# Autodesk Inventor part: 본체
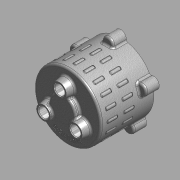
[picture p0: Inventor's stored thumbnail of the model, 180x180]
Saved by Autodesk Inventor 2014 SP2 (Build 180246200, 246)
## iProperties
Created: 2015-11
Part Number: 본체
Document SubType Name: 모델링
Designer: mdu
Material: 알루미늄 6061
Density: 1 g/cm^3
Appearance: 알루미늄 - 평지
변환 표준: STEP AP214IS
파일 이름: C:\Users\SeoGD\Desktop\?쒗뿕\紐몄껜.stp
전처리기: Build: 253, Release: 2010 SP1 - Date: Wed 07/29/2009
전송 단위: 밀리미터
불확실성: 0.01
Author: mdu
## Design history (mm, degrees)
sketch "스케치2"
  geometry: C1 r 50 at (0, 0); 1 further point
  constraints: 1 centre point, 1 coincident
  dimensions: "d9" = 100 diameter of C1
extrude "돌출2" new body sketch "스케치2" distance "d10" = 80; taper "d11" = 0 deg
feature "쉘1" dims "d12" = 5
sketch "스케치3" dims "d13" = 55
  geometry: C1 r 7.5 at (0, 27.5); C2 r 12.5 at (0, 27.5); 2 further points
  constraints: 2 centre point, 2 coincident, 2 vertical alignment, 2 other
  dimensions: "d14" = 15 diameter of C1; "d15" = 25 diameter of C2
extrude "돌출3" join sketch "스케치3" distance "d16" = 12; taper "d17" = -10 deg
hole "구멍2" diameter "d20" = 15; stored, may be unused: countersink angle "d24" = 90 deg, drill point angle "d26" = 118 deg; dims "d18" = 10, "d19" = 10, "d21" = 6, "d22" = 4, "d23" = 2, "d25" = 15
chamfer "모따기1" distance "d27" = 1; stored, may be unused: second distance "d28" = 2, angle "d29" = 45 deg
sketch "스케치4"
  geometry: L1 (0, 0)-(0, 88); L2 (0, 70)-(13.16, 70); L3 (-45, 75)-(45, 75) reference; L4 (-50, 80)-(50, 80) reference; L5 (13.16, 70)-(14.5, 75); L6 (20, 80)-(20, 88); L7 (20, 88)-(0, 88); L8 (20, 80)-(14.5, 75)
  constraints: 12 end point, 3 point on line, 2 perpendicular, 1 vertical
  dimensions: "d34" = 40 diameter of L6 L1; "d35" = 105 deg angle of L5 L3; "d36" = 5 distance between parallel lines of L2 L3; "d37" = 8 distance between parallel lines of L7 L4; "d51" = 29 diameter of L5.end L1
revolve "회전1" sketch "스케치4" stored, may be unused: angle "d38" = 90 deg
hole "구멍3" diameter "d41" = 15; stored, may be unused: countersink angle "d45" = 90 deg, drill point angle "d47" = 0 deg; dims "d39" = 10, "d40" = 10, "d42" = 6, "d43" = 22, "d44" = 13, "d46" = 15
chamfer "모따기2" distance "d48" = 1; stored, may be unused: second distance "d49" = 2, angle "d50" = 45 deg
fillet "모깎기1" dims "d52" = 3
fillet "모깎기2" dims "d53" = 3, "d72" = 0.2
sketch "스케치5"
  geometry: A1 r 50 centre (0, 0) between (50, 0) and (-8.074, 49.344) reference; A2 r 8.5 centre (0, 52) between (8.074, 49.344) and (-8.074, 49.344); 1 further point
  constraints: 5 point on circle, 1 centre point, 1 horizontal alignment
  dimensions: "d54" = 90 deg dimension on point (0, 0) A2.centre A1.start; "d55" = 52 distance of A2.centre point (0, 0); "d56" = 17 diameter of A2
extrude "돌출4" join sketch "스케치5" distance "d57" = 20; taper "d58" = 0 deg
fillet "모깎기3" dims "d59" = 3
hole "구멍4" diameter "d62" = 4.134; stored, may be unused: countersink angle "d66" = 90 deg, drill point angle "d68" = 118 deg; dims "d60" = 10, "d61" = 10, "d63" = 12, "d64" = 22, "d65" = 13, "d67" = 15
sketch "스케치6"
  geometry: C1 r 47 at (0, 0) reference; C2 r 42.5 at (0, 0); 1 further point
  constraints: 1 centre point, 1 coincident, 1 other
  dimensions: "d73" = 85 diameter of C2
feature "엠보싱1" sketch "스케치6" dims "d74" = 0.5, "d75" = 0
node "작업 평면1"
sketch "스케치7"
  geometry: A1 r 50 centre (0, 0) between (5.144, 49.735) and (-5.144, 49.735) reference; A2 r 3 centre (0, 47.916) between (2.204, 49.951) and (-2.204, 49.951); 1 further point
  constraints: 4 point on circle, 1 centre point, 1 vertical alignment
  dimensions: "d77" = 3 radius of A2
extrude "돌출5" join sketch "스케치7" distance "d79" = 15; taper "d80" = 0 deg
fillet "모깎기4" dims "d81" = 1
fillet "모깎기5" dims "d82" = 1
node "솔리드1"
node "솔리드 본체"
node "곡면 본체"
pattern_circular "원형 패턴1" dims "d31" = 360 deg
pattern_circular "원형 패턴2" dims "d70" = 360 deg
pattern_circular "원형 패턴3" dims "d84" = 360 deg
pattern_linear "직사각형 패턴1" dims "d89" = 25
node "솔리드2"
